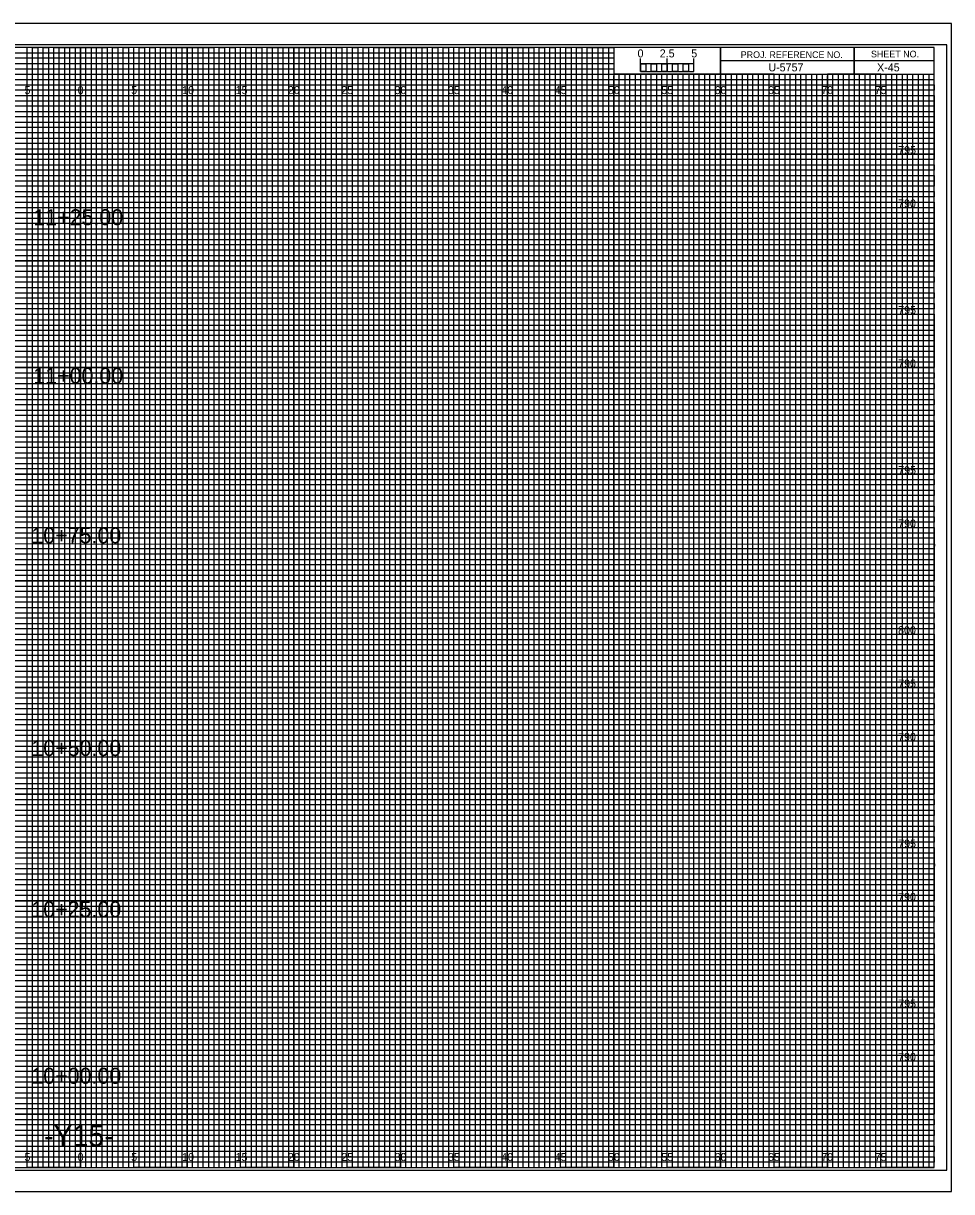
# Model space of a CAD drawing. Extents: x -7 to 162, y -2 to 107.
# Drawn here: x 74.6 to 161.7, y -2.3 to 107.3 of the extents above; entities that cross this region are included whole.
import ezdxf

# ---------------------------------------------------------------- set-up
doc = ezdxf.new("R2010")
doc.units = 0
for name, color, linetype in [('Exist Cross Section Cell', 7, 'Continuous'), ('Exist XS Center Line Elevation Label', 7, 'Continuous'), ('Prop CMT Conc Surface', 7, 'Continuous'), ('Prop CMT Concrete Structures', 7, 'Continuous'), ('Prop CMT Pvmt Course 1', 7, 'Continuous'), ('Prop CMT Pvmt Course 1 CG', 7, 'Continuous'), ('Prop CMT Pvmt Course 1 Wedge', 7, 'Continuous'), ('Prop CMT Pvmt Course 2', 7, 'Continuous'), ('Prop CMT Pvmt Course 3', 7, 'Continuous'), ('Prop CMT Pvmt Surface', 7, 'Continuous'), ('Prop CMT Pvmt Wedge Surface 2', 7, 'Continuous'), ('Prop CMT Pvmt Wedge Surface 3', 7, 'Continuous'), ('Prop CMT Shld Paved Course 1', 7, 'Continuous'), ('Prop CMT Shld Paved Course 2', 7, 'Continuous'), ('Prop CMT Shld Paved Course 3', 7, 'Continuous'), ('Prop CMT Slope Grass', 7, 'Continuous'), ('Prop CMT Subgrade Earthwork', 7, 'Continuous')]:
    doc.layers.add(name, color=color, linetype=linetype)

msp = doc.modelspace()

# ---------------------------------------------------------------- linework, layer by layer
at = {"layer": 'Exist Cross Section Cell'}
for p, q in [((75, 105), (70, 105)), ((75, 0), (75, 105)), ((85, 105), (80, 105)), ((80, 105), (80, 0)), ((85, 0), (85, 105)), ((95, 105), (90, 105)), ((90, 105), (90, 0)), ((95, 0), (95, 105)), ((105, 105), (100, 105)), ((100, 105), (100, 0)), ((105, 0), (105, 105)), ((115, 105), (110, 105)), ((110, 105), (110, 0)), ((115, 0), (115, 105)), ((125, 105), (120, 105)), ((120, 105), (120, 0)), ((125, 0), (125, 105)), ((130, 105), (130, 0)), ((135, 0), (135, 102.5)), ((145, 102.5), (140, 102.5)), ((140, 102.5), (140, 0)), ((145, 0), (145, 102.5)), ((155, 102.5), (150, 102.5)), ((150, 102.5), (150, 0)), ((155, 0), (155, 102.5)), ((80, 0), (75, 0)), ((90, 0), (85, 0)), ((100, 0), (95, 0)), ((110, 0), (105, 0)), ((120, 0), (115, 0)), ((130, 0), (125, 0)), ((140, 0), (135, 0)), ((150, 0), (145, 0)), ((160, 0), (155, 0)), ((160, 0), (160, 0))]:
    msp.add_line(p, q, dxfattribs=at)
for points in [[(0, 100), (160, 100), (160, 95), (0, 95)], [(0, 90), (160, 90), (160, 85), (0, 85)], [(0, 80), (160, 80), (160, 75), (0, 75)], [(0, 70), (160, 70), (160, 65), (0, 65)], [(0, 60), (160, 60), (160, 55), (0, 55)], [(0, 50), (160, 50), (160, 45), (0, 45)], [(0, 40), (160, 40), (160, 35), (0, 35)], [(0, 30), (160, 30), (160, 25), (0, 25)], [(0, 20), (160, 20), (160, 15), (0, 15)], [(0, 10), (160, 10), (160, 5), (0, 5)]]:
    msp.add_lwpolyline(points, dxfattribs=at)
at = {"layer": 'Exist XS Center Line Elevation Label'}
for points in [[(72.5, 0), (77.5, 0), (77.5, 105), (82.5, 105), (82.5, 0), (87.5, 0), (87.5, 105), (92.5, 105), (92.5, 0), (97.5, 0), (97.5, 105), (102.5, 105), (102.5, 0), (107.5, 0), (107.5, 105), (112.5, 105), (112.5, 0), (117.5, 0), (117.5, 105), (122.5, 105), (122.5, 0), (127.5, 0), (127.5, 105), (129.97, 105), (130, 105), (130, 102.5), (132.5, 102.5), (132.5, 0), (137.5, 0), (137.5, 102.5), (142.5, 102.5), (142.5, 0), (147.5, 0), (147.5, 102.5), (152.5, 102.5), (152.5, 0), (157.5, 0), (157.5, 102.5)], [(0, 102.5), (137.5, 102.5)], [(0, 92.5), (160, 92.5), (160, 97.5), (0, 97.5)], [(0, 82.5), (160, 82.5), (160, 87.5), (0, 87.5)], [(0, 72.5), (160, 72.5), (160, 77.5), (0, 77.5)], [(0, 62.5), (160, 62.5), (160, 67.5), (0, 67.5)], [(0, 52.5), (160, 52.5), (160, 57.5), (0, 57.5)], [(0, 42.5), (160, 42.5), (160, 47.5), (0, 47.5)], [(0, 32.5), (160, 32.5), (160, 37.5), (0, 37.5)], [(0, 22.5), (160, 22.5), (160, 27.5), (0, 27.5)], [(0, 12.5), (160, 12.5), (160, 17.5), (0, 17.5)], [(0, 2.5), (160, 2.5), (160, 7.5), (0, 7.5)]]:
    msp.add_lwpolyline(points, dxfattribs=at)
at = {"layer": 'Prop CMT Conc Surface'}
for p, q in [((75, 0), (75, 105)), ((80, 0), (80, 105)), ((85, 0), (85, 105)), ((90, 0), (90, 105)), ((95, 0), (95, 105)), ((100, 0), (100, 105)), ((105, 0), (105, 105)), ((110, 0), (110, 105)), ((115, 0), (115, 105)), ((120, 0), (120, 105)), ((125, 0), (125, 105)), ((130, 0), (130, 102.34)), ((135, 0), (135, 102.34)), ((140, 0), (140, 102.34)), ((145, 0), (145, 102.34)), ((150, 0), (150, 102.34)), ((155, 0), (155, 102.34)), ((0, 100), (160, 100)), ((0, 95), (160, 95)), ((0, 90), (160, 90)), ((0, 85), (160, 85)), ((0, 80), (160, 80)), ((0, 75), (160, 75)), ((0, 70), (160, 70)), ((0, 65), (160, 65)), ((0, 60), (160, 60)), ((0, 55), (160, 55)), ((0, 50), (160, 50)), ((0, 45), (160, 45)), ((0, 40), (160, 40)), ((0, 35), (160, 35)), ((0, 30), (160, 30)), ((0, 25), (160, 25)), ((0, 20), (160, 20)), ((0, 15), (160, 15)), ((0, 10), (160, 10)), ((0, 5), (160, 5))]:
    msp.add_line(p, q, dxfattribs=at)
at = {"layer": 'Prop CMT Concrete Structures'}
for p, q in [((133.5, 102.5), (133, 102.5)), ((133, 102.5), (133, 0)), ((133.5, 0), (133.5, 102.5)), ((134.5, 102.5), (134, 102.5)), ((134, 102.5), (134, 0)), ((134.5, 0), (134.5, 102.5)), ((133, 0), (132.5, 0)), ((134, 0), (133.5, 0))]:
    msp.add_line(p, q, dxfattribs=at)
for points in [[(75, 0), (75.5, 0), (75.5, 105), (76, 105), (76, 0)], [(76, 0), (76.5, 0), (76.5, 105), (77, 105), (77, 0)], [(77.5, 0), (78, 0), (78, 105), (78.5, 105), (78.5, 0)], [(78.5, 0), (79, 0), (79, 105), (79.5, 105), (79.5, 0)], [(80, 0), (80.5, 0), (80.5, 105), (81, 105), (81, 0)], [(81, 0), (81.5, 0), (81.5, 105), (82, 105), (82, 0)], [(82.5, 0), (83, 0), (83, 105), (83.5, 105), (83.5, 0)], [(83.5, 0), (84, 0), (84, 105), (84.5, 105), (84.5, 0)], [(85, 0), (85.5, 0), (85.5, 105), (86, 105), (86, 0)], [(86, 0), (86.5, 0), (86.5, 105), (87, 105), (87, 0)], [(87.5, 0), (88, 0), (88, 105), (88.5, 105), (88.5, 0)], [(88.5, 0), (89, 0), (89, 105), (89.5, 105), (89.5, 0)], [(90, 0), (90.5, 0), (90.5, 105), (91, 105), (91, 0)], [(91, 0), (91.5, 0), (91.5, 105), (92, 105), (92, 0)], [(92.5, 0), (93, 0), (93, 105), (93.5, 105), (93.5, 0)], [(93.5, 0), (94, 0), (94, 105), (94.5, 105), (94.5, 0)], [(95, 0), (95.5, 0), (95.5, 105), (96, 105), (96, 0)], [(96, 0), (96.5, 0), (96.5, 105), (97, 105), (97, 0)], [(97.5, 0), (98, 0), (98, 105), (98.5, 105), (98.5, 0)], [(98.5, 0), (99, 0), (99, 105), (99.5, 105), (99.5, 0)], [(100, 0), (100.5, 0), (100.5, 105), (101, 105), (101, 0)], [(101, 0), (101.5, 0), (101.5, 105), (102, 105), (102, 0)], [(102.5, 0), (103, 0), (103, 105), (103.5, 105), (103.5, 0)], [(103.5, 0), (104, 0), (104, 105), (104.5, 105), (104.5, 0)], [(105, 0), (105.5, 0), (105.5, 105), (106, 105), (106, 0)], [(106, 0), (106.5, 0), (106.5, 105), (107, 105), (107, 0)], [(107.5, 0), (108, 0), (108, 105), (108.5, 105), (108.5, 0)], [(108.5, 0), (109, 0), (109, 105), (109.5, 105), (109.5, 0)], [(110, 0), (110.5, 0), (110.5, 105), (111, 105), (111, 0)], [(111, 0), (111.5, 0), (111.5, 105), (112, 105), (112, 0)], [(112.5, 0), (113, 0), (113, 105), (113.5, 105), (113.5, 0)], [(113.5, 0), (114, 0), (114, 105), (114.5, 105), (114.5, 0)], [(115, 0), (115.5, 0), (115.5, 105), (116, 105), (116, 0)], [(116, 0), (116.5, 0), (116.5, 105), (117, 105), (117, 0)], [(117.5, 0), (118, 0), (118, 105), (118.5, 105), (118.5, 0)], [(118.5, 0), (119, 0), (119, 105), (119.5, 105), (119.5, 0)], [(120, 0), (120.5, 0), (120.5, 105), (121, 105), (121, 0)], [(121, 0), (121.5, 0), (121.5, 105), (122, 105), (122, 0)], [(122.5, 0), (123, 0), (123, 105), (123.5, 105), (123.5, 0)], [(123.5, 0), (124, 0), (124, 105), (124.5, 105), (124.5, 0)], [(125, 0), (125.5, 0), (125.5, 105), (126, 105), (126, 0)], [(126, 0), (126.5, 0), (126.5, 105), (127, 105), (127, 0)], [(127.5, 0), (128, 0), (128, 105), (128.5, 105), (128.5, 0)], [(128.5, 0), (129, 0), (129, 105), (129.5, 105), (129.5, 0)], [(130, 0), (130.5, 0), (130.5, 102.5), (131.01, 102.5), (131.01, 0)], [(131, 0), (131.5, 0), (131.5, 102.5), (132, 102.5), (132, 0)], [(135, 0), (135.49, 0), (135.49, 102.5), (136, 102.5), (136, 0)], [(136, 0), (136.5, 0), (136.5, 102.5), (137.03, 102.5), (137.03, 0)], [(137.5, 0), (138, 0), (138, 102.5), (138.5, 102.5), (138.5, 0)], [(138.5, 0), (139, 0), (139, 102.5), (139.5, 102.5), (139.5, 0)], [(140, 0), (140.5, 0), (140.5, 102.5), (141, 102.5), (141, 0)], [(141, 0), (141.5, 0), (141.5, 102.5), (142, 102.5), (142, 0)], [(142.5, 0), (143, 0), (143, 102.5), (143.5, 102.5), (143.5, 0)], [(143.5, 0), (144, 0), (144, 102.5), (144.5, 102.5), (144.5, 0)], [(145, 0), (145.5, 0), (145.5, 102.5), (146, 102.5), (146, 0)], [(146, 0), (146.5, 0), (146.5, 102.5), (147, 102.5), (147, 0)], [(147.5, 0), (148, 0), (148, 102.5), (148.5, 102.5), (148.5, 0)], [(148.5, 0), (149, 0), (149, 102.5), (149.5, 102.5), (149.5, 0)], [(150, 0), (150.5, 0), (150.5, 102.5), (151, 102.5), (151, 0)], [(151, 0), (151.5, 0), (151.5, 102.5), (152, 102.5), (152, 0)], [(152.5, 0), (153, 0), (153, 102.5), (153.5, 102.5), (153.5, 0)], [(153.5, 0), (154, 0), (154, 102.5), (154.5, 102.5), (154.5, 0)], [(155, 0), (155.5, 0), (155.5, 102.5), (156, 102.5), (156, 0)], [(156, 0), (156.5, 0), (156.5, 102.5), (157, 102.5), (157, 0)], [(157.5, 0), (158, 0), (158, 102.5), (158.5, 102.5), (158.5, 0)], [(158.5, 0), (159, 0), (159, 102.5), (159.5, 102.5), (159.5, 0)]]:
    msp.add_lwpolyline(points, dxfattribs=at)
at = {"layer": 'Prop CMT Pvmt Course 1'}
msp.add_lwpolyline([(-5.4, -0.25), (161.2, -0.25), (161.2, 105.25), (-5.4, 105.25)], close=True, dxfattribs=at)
at = {"layer": 'Prop CMT Pvmt Course 1 CG'}
msp.add_lwpolyline([(-6.7, -2.25), (161.65, -2.25), (161.65, 107.25), (-6.7, 107.25)], close=True, dxfattribs=at)
at = {"layer": 'Prop CMT Pvmt Course 2'}
for p, q in [((0, 104.5), (130, 104.5)), ((130, 104.5), (130, 103.99)), ((130, 103.99), (0, 103.99)), ((0, 103.5), (130, 103.5)), ((130, 102.95), (0, 102.95)), ((130, 103.5), (130, 102.95)), ((0, 102), (160, 102))]:
    msp.add_line(p, q, dxfattribs=at)
for points in [[(0, 101.5), (135, 101.5), (160, 101.5), (160, 101), (0, 101)], [(0, 100.5), (160, 100.5), (160, 99.5), (0, 99.5)], [(0, 99), (160, 99), (160, 98.5), (0, 98.49)], [(0, 98), (160, 98), (160, 97), (0, 97)], [(0, 96.5), (160, 96.5), (160, 96), (0, 96)], [(0, 95.5), (160, 95.5), (160, 94.5), (0, 94.5)], [(0, 94), (160, 94), (160, 93.5), (0, 93.5)], [(0, 93), (160, 93), (160, 92), (0, 92)], [(0, 91.5), (160, 91.5), (160, 91), (0, 91)], [(0, 90.5), (160, 90.5), (160, 89.5), (0, 89.5)], [(0, 89), (160, 89), (160, 88.5), (0, 88.5)], [(0, 88), (160, 88), (160, 86.98), (160, 86.5), (160, 86), (0, 86)], [(0, 87), (160, 87), (160, 86.5), (0, 86.5)], [(0, 85.5), (160, 85.5), (160, 84.5), (0, 84.52)], [(0, 84.52), (160, 84.5), (160, 84), (0, 84)], [(0, 83.5), (160, 83.5), (160, 83), (0, 83)], [(0, 82), (160, 82), (160, 81.5), (0, 81.5)], [(0, 81), (160, 81), (160, 80.5), (0, 80.5)], [(-0.04, 79.45), (160, 79.45), (160, 78.94), (-0.04, 78.94)], [(0, 78.5), (160, 78.5), (160, 78), (0, 78)], [(0, 77), (160, 77), (160, 76.5), (0, 76.5)], [(0, 76), (160, 76), (160, 75.5), (0, 75.5)], [(0, 74.5), (160, 74.5), (160, 74), (0, 74)], [(0, 73.5), (160, 73.5), (160, 73), (0, 73)], [(0, 72), (160, 72), (160, 71.5), (0, 71.5)], [(0, 71), (160, 71), (160, 70.5), (0, 70.5)], [(0, 69.5), (160, 69.5), (160, 68.99), (0, 69)], [(0, 68.5), (160, 68.5), (160, 68), (0, 68)], [(0, 67), (160, 67), (160, 66.5), (0, 66.5)], [(0, 66), (160, 66), (160, 65.5), (0, 65.5)], [(0, 64.5), (160, 64.5), (160, 64), (0, 64)], [(0, 63.5), (160, 63.5), (160, 63), (0, 63)], [(0, 62), (160, 62), (160, 61.5), (0, 61.5)], [(0, 61), (160, 61), (160, 60.5), (0, 60.5)], [(0, 59.5), (160, 59.5), (160, 59), (0, 59)], [(0, 58.5), (160.03, 58.45), (160, 58), (0, 58)], [(0, 57), (160, 57), (160, 56.5), (0, 56.5)], [(0, 56), (160, 56), (160, 55.5), (0, 55.5)], [(0, 54.5), (160, 54.5), (160, 54), (0, 54)], [(0, 53.5), (160, 53.5), (160, 53), (0, 53)], [(0, 52), (160, 52), (160, 51.5), (0, 51.5)], [(0, 51), (160, 51), (160, 50.5), (0, 50.5)], [(0, 49.5), (160, 49.5), (160, 49), (0, 49)], [(0, 48.5), (160, 48.5), (160, 48), (0, 48)], [(0, 47), (160, 47), (160, 46.5), (0, 46.5)], [(0, 46), (160, 46), (160, 45.5), (0, 45.5)], [(0, 44.5), (160, 44.5), (160, 44), (0, 44)], [(0, 43.5), (160, 43.5), (160, 43), (0, 43)], [(0, 42), (160, 42), (160, 41.5), (0, 41.5)], [(0, 41), (160, 41), (160, 40.5), (0, 40.5)], [(0, 39.5), (160, 39.5), (160, 38.99), (0, 39)], [(0, 38.5), (160, 38.5), (160, 38), (0, 38)], [(0, 37), (160, 37), (160, 36.5), (0, 36.5)], [(0, 36), (160, 36), (160, 35.5), (0, 35.5)], [(0, 34.5), (160, 34.5), (160, 34), (0, 34)], [(0, 33.5), (160, 33.5), (160, 33), (0, 33)], [(0, 32), (160, 32), (160, 31.5), (0, 31.5)], [(0, 31), (160, 31), (160, 30.5), (0, 30.5)], [(0, 29.5), (160, 29.5), (160, 29), (0, 29)], [(0, 28.5), (160.03, 28.46), (160, 28), (0, 28)], [(0, 27), (160, 27), (160, 26.5), (0, 26.5)], [(0, 26), (160, 26), (160, 25.5), (0, 25.5)], [(0, 24.5), (160, 24.5), (160, 24), (0, 24)], [(0, 23.5), (160, 23.5), (160, 23), (0, 23)], [(0, 22), (160, 22), (160, 21.5), (0, 21.5)], [(0, 21), (160, 21), (160, 20.5), (0, 20.5)], [(0, 19.5), (160, 19.5), (160, 19), (0, 19)], [(0, 18.5), (160, 18.5), (160, 18), (0, 18)], [(0, 17), (160, 17), (160, 16.5), (0, 16.5)], [(0, 16), (160, 16), (160, 15.5), (0, 15.5)], [(0, 14.5), (160, 14.5), (160, 14), (0, 14)], [(0, 13.5), (160, 13.5), (160, 13), (0, 13)], [(0, 12), (160, 12), (160, 11.5), (0, 11.5)], [(0, 11), (160, 11), (160, 10.5), (0, 10.5)], [(0, 9.5), (160, 9.5), (160, 9), (0, 9)], [(0, 8.5), (160, 8.5), (160, 8), (0, 8)], [(0, 7), (160, 7), (160, 6.5), (0, 6.5)], [(0, 6), (160, 6), (160, 5.5), (0, 5.5)], [(0, 4.5), (160, 4.5), (160, 4), (0, 4)], [(0, 3.5), (160, 3.5), (160, 3), (0, 3)], [(0, 2), (160, 2), (160, 1.5), (0, 1.5)], [(0, 1), (160, 1), (160, 0.5), (0, 0.5)]]:
    msp.add_lwpolyline(points, dxfattribs=at)
at = {"layer": 'Prop CMT Pvmt Course 3'}
for p, q in [((152.5, 105), (152.5, 102.5)), ((152.5, 102.5), (152.5, 105)), ((160, 103.75), (140, 103.75)), ((140, 103.75), (140, 102.5)), ((140, 102.5), (160, 102.5))]:
    msp.add_line(p, q, dxfattribs=at)
for points in [[(160, 105), (0, 105), (0, 0), (160, 0)], [(140, 105), (130, 105), (130, 102.52), (140, 102.52)], [(160, 105), (140, 105), (140, 102.5), (160, 102.5)]]:
    msp.add_lwpolyline(points, close=True, dxfattribs=at)
at = {"layer": 'Prop CMT Pvmt Surface'}
for p, q in [((132.5, 102.75), (132.5, 103.95)), ((132.5, 103.45), (132.5, 103.95)), ((135, 102.75), (135, 103.95)), ((137.5, 102.75), (137.5, 103.95)), ((137.5, 103.45), (137.5, 103.95))]:
    msp.add_line(p, q, dxfattribs=at)
for points in [[(137.5, 103.45), (132.5, 103.45), (132.5, 102.75), (137.5, 102.75)], [(132.5, 103.45), (133, 103.45), (133, 102.75), (132.5, 102.75)], [(133.5, 103.45), (134, 103.45), (134, 102.75), (133.5, 102.75)], [(134.5, 103.45), (135, 103.45), (135, 102.75), (134.5, 102.75)], [(135.5, 103.45), (136, 103.45), (136, 102.75), (135.5, 102.75)], [(136.5, 103.45), (137, 103.45), (137, 102.75), (136.5, 102.75)]]:
    msp.add_lwpolyline(points, close=True, dxfattribs=at)
at = {"layer": 'Prop CMT Subgrade Earthwork'}
for p, q in [((161.65, 107.25), (-6.7, 107.25)), ((-6.7, -2.25), (161.65, -2.25))]:
    msp.add_line(p, q, dxfattribs=at)

# ---------------------------------------------------------------- texts
at = {"layer": 'Prop CMT Pvmt Course 1 Wedge'}
for s, p in [('5', (74.74, 100.62)), ('0', (79.73, 100.62)), ('0', (79.73, 100.62)), ('5', (84.74, 100.62)), ('10', (89.52, 100.62)), ('15', (94.53, 100.62)), ('20', (99.43, 100.62)), ('25', (104.44, 100.62)), ('30', (109.43, 100.62)), ('35', (114.44, 100.62)), ('40', (119.43, 100.62)), ('45', (124.44, 100.62)), ('50', (129.43, 100.62)), ('55', (134.44, 100.62)), ('60', (139.43, 100.62)), ('65', (144.44, 100.62)), ('70', (149.43, 100.62)), ('75', (154.44, 100.62)), ('5', (74.74, 0.62)), ('0', (79.73, 0.62)), ('0', (79.73, 0.62)), ('5', (84.74, 0.62)), ('10', (89.52, 0.62)), ('15', (94.53, 0.62)), ('20', (99.43, 0.62)), ('25', (104.44, 0.62)), ('30', (109.43, 0.62)), ('35', (114.44, 0.62)), ('40', (119.43, 0.62)), ('45', (124.44, 0.62)), ('50', (129.43, 0.62)), ('55', (134.44, 0.62)), ('60', (139.43, 0.62)), ('65', (144.44, 0.62)), ('70', (149.43, 0.62)), ('75', (154.44, 0.62))]:
    msp.add_text(s, height=0.75, dxfattribs=at).set_placement(p)
at = {"layer": 'Prop CMT Pvmt Course 3'}
for s, p in [('PROJ. REFERENCE NO.', (141.88, 104)), ('SHEET NO.', (154.09, 104.06))]:
    msp.add_text(s, height=0.625, dxfattribs=at).set_placement(p)
at = {"layer": 'Prop CMT Pvmt Surface'}
msp.add_text('0', height=0.75, dxfattribs=at).set_placement((132.21, 104.06))
at = {"layer": 'Prop CMT Pvmt Wedge Surface 2'}
msp.add_text('-Y15-', height=2, dxfattribs=at).set_placement((76.57, 2))
at = {"layer": 'Prop CMT Pvmt Wedge Surface 3'}
for s, p in [('2.5', (134.29, 104.06)), ('5', (137.24, 104.06))]:
    msp.add_text(s, height=0.75, dxfattribs=at).set_placement(p)
at = {"layer": 'Prop CMT Shld Paved Course 1'}
for s, p in [('11+25.00', (75.57, 88.33)), ('11+00.00', (75.57, 73.48)), ('10+75.00', (75.39, 58.51)), ('10+50.00', (75.39, 38.58)), ('10+25.00', (75.39, 23.46)), ('10+00.00', (75.39, 7.86))]:
    msp.add_text(s, height=1.5, dxfattribs=at).set_placement(p)
at = {"layer": 'Prop CMT Shld Paved Course 2'}
msp.add_text('X-45', height=0.75, dxfattribs=at).set_placement((154.66, 102.75))
at = {"layer": 'Prop CMT Shld Paved Course 3'}
msp.add_text('U-5757', height=0.75, dxfattribs=at).set_placement((144.47, 102.75))
at = {"layer": 'Prop CMT Slope Grass'}
for s, p in [('795', (156.64, 95)), ('790', (156.63, 90)), ('795', (156.64, 80)), ('790', (156.63, 75)), ('795', (156.64, 65)), ('790', (156.63, 60)), ('800', (156.63, 50)), ('795', (156.64, 45)), ('790', (156.63, 40)), ('795', (156.64, 30)), ('790', (156.63, 25)), ('795', (156.64, 15)), ('790', (156.63, 10))]:
    msp.add_text(s, height=0.75, dxfattribs=at).set_placement(p)

doc.saveas('drawing.dxf')
